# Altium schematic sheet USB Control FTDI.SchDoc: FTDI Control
size 431 x 279 mm; Date: Not shown in title block; ApprovedBy: Not shown in title block; CheckedBy: Not shown in title block; Author: Not shown in title block; CompanyName: Not shown in title block; Engineer: Not shown in title block; Organization: Not shown in title block; Address1: Not shown in title block; Address2: Not shown in title block; Address3: Not shown in title block; Address4: Not shown in title block; DocumentNumber: 1; Revision: Use project parameter SCH_Rev; SheetNumber: 6; SheetTotal: 15; PageSetup: Record=PageOptions¦CenterHorizontal=True¦CenterVertical=True¦PrintScale=1.00¦XCorrection=1.00¦YCorrection=1.00¦PrintKind=0¦BorderSize=5000000¦LeftOffset=0¦BottomOffset=0¦Orientation=2¦PaperLength=1000¦PaperWidth=1000¦Scale=100¦PaperSource=15¦PrintQuality=600¦MediaType=1¦DitherType=10¦PaperKind=Letter¦PrintScaleMode=1
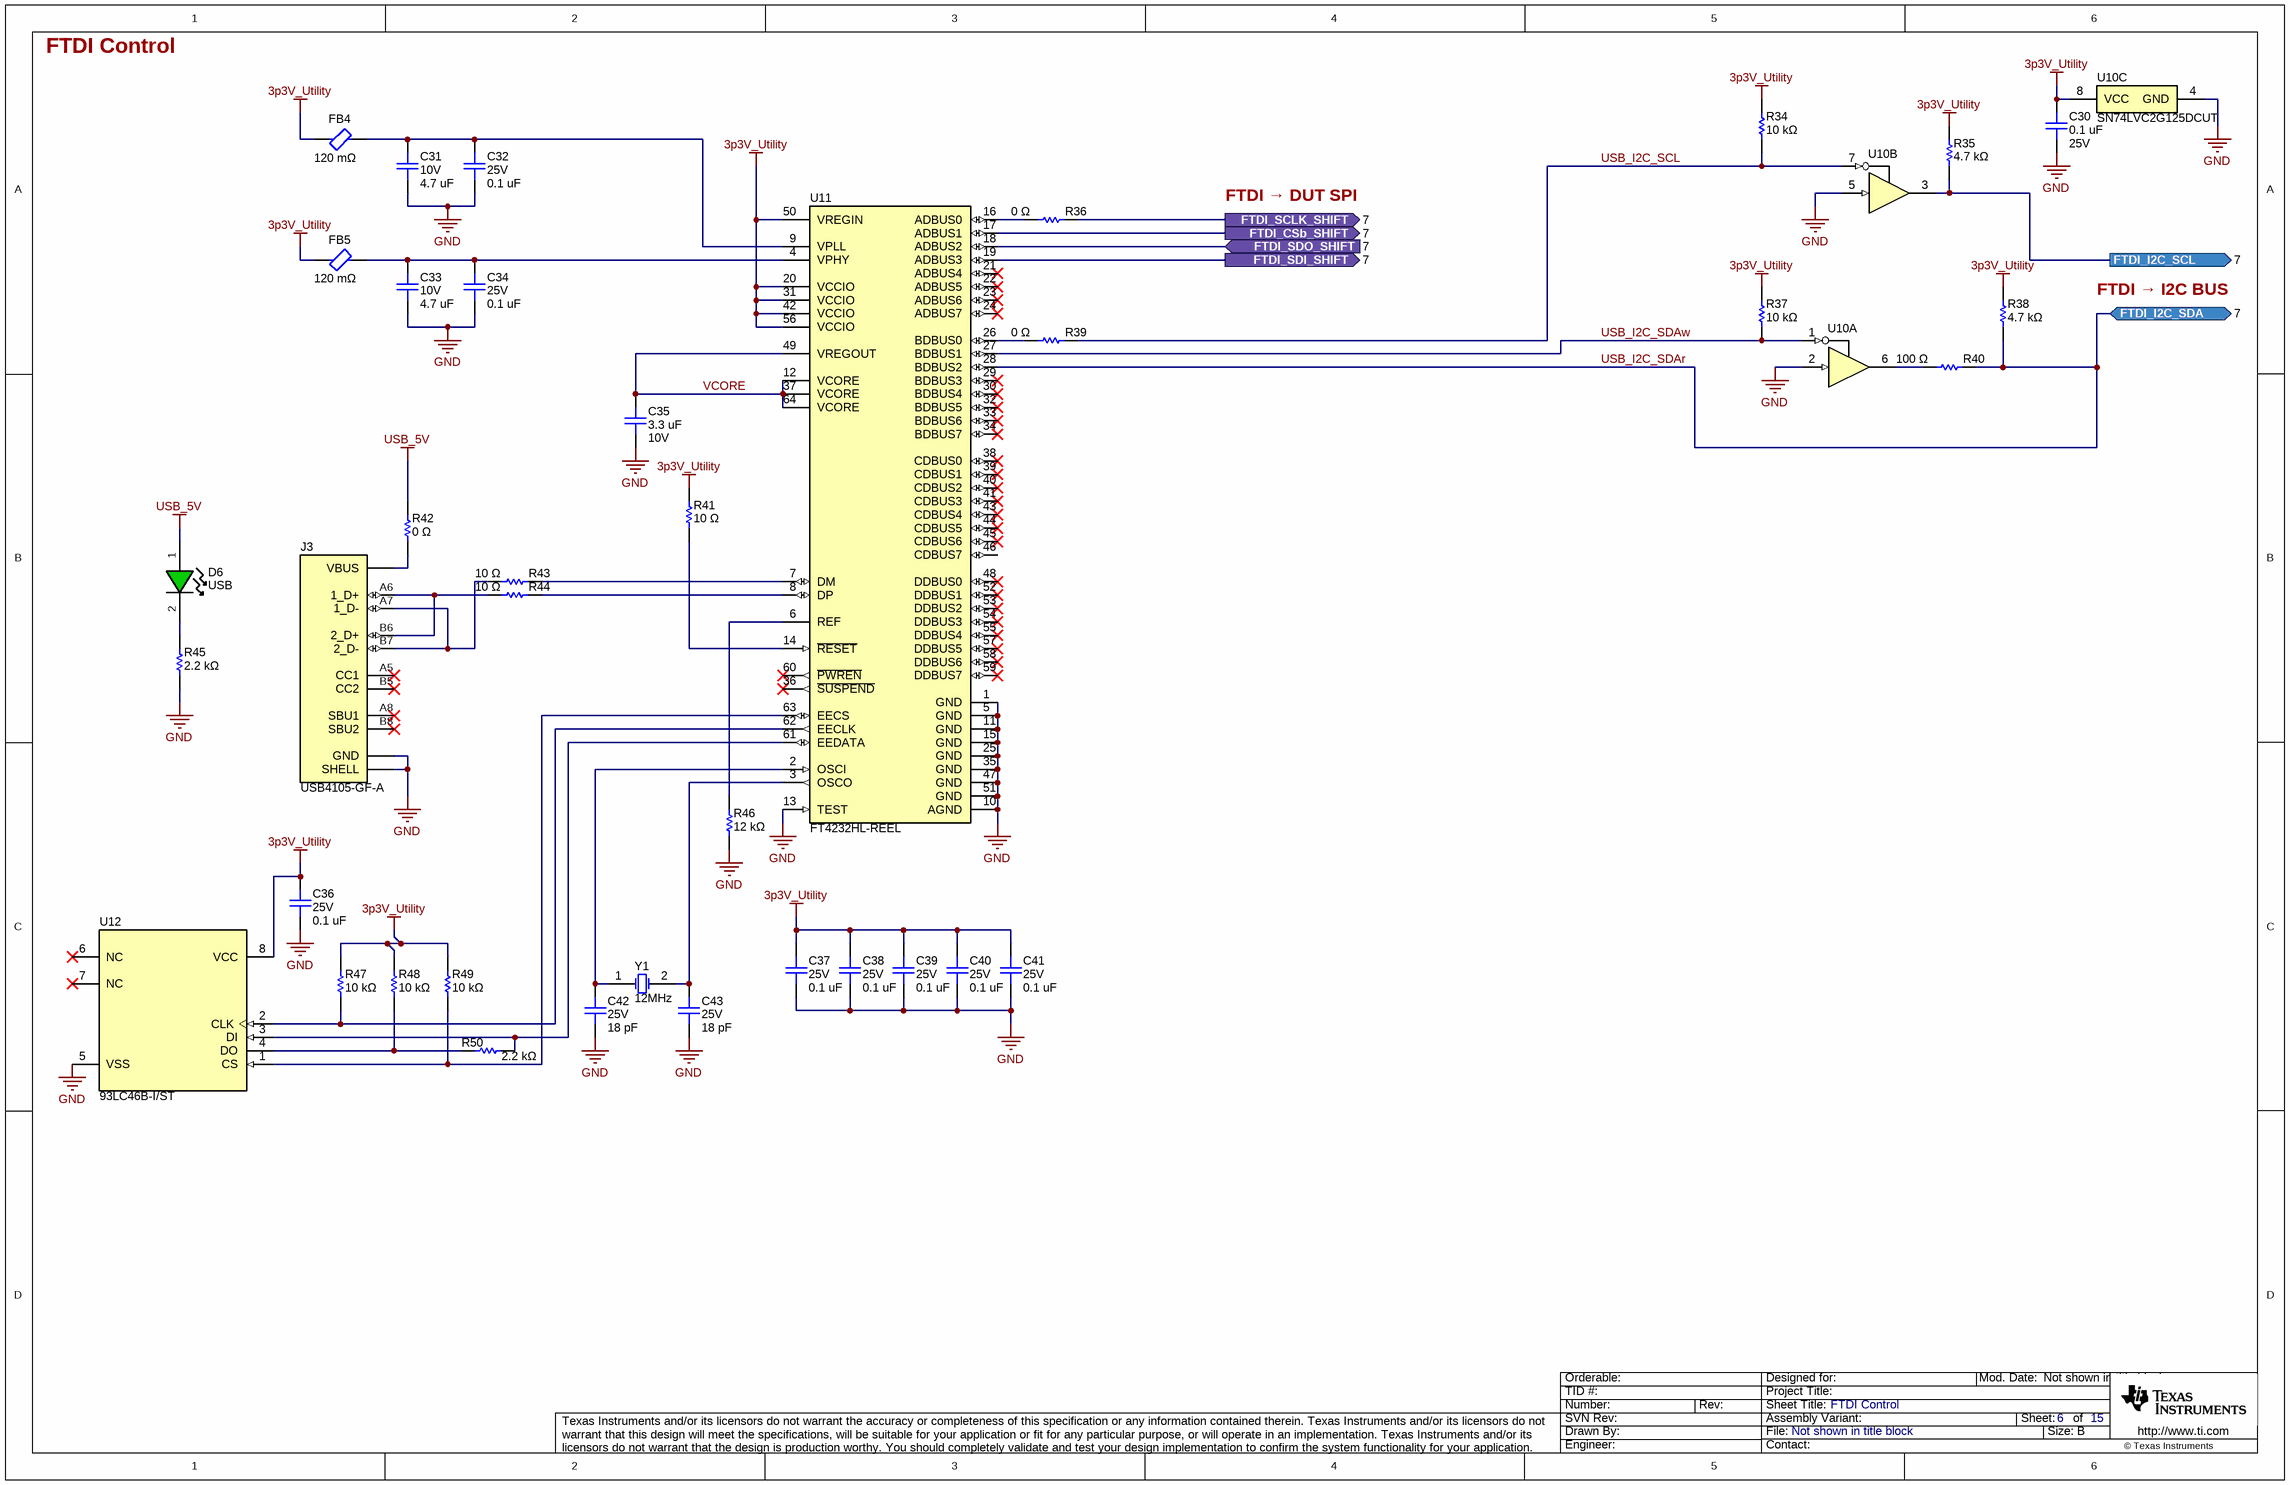
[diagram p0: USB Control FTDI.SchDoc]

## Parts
C30  value 0.1 uF  Voltage - Rated: 25V  [0402L_cap]  (hidden comment: GRT155R71E104KE01J)
C31  value 4.7 uF  Voltage - Rated: 10V  [0402L_cap]  (hidden comment: C1005X5R1A475K050BC)
C32  value 0.1 uF  Voltage - Rated: 25V  [0402L_cap]  (hidden comment: GRT155R71E104KE01J)
C33  value 4.7 uF  Voltage - Rated: 10V  [0402L_cap]  (hidden comment: C1005X5R1A475K050BC)
C34  value 0.1 uF  Voltage - Rated: 25V  [0402L_cap]  (hidden comment: GRT155R71E104KE01J)
C35  value 3.3 uF  Voltage - Rated: 10V  [0603L_cap]  (hidden comment: CGA3E1X5R1A335K080AC)
C36  value 0.1 uF  Voltage - Rated: 25V  [0402L_cap]  (hidden comment: GRT155R71E104KE01J)
C37  value 0.1 uF  Voltage - Rated: 25V  [0402L_cap]  (hidden comment: GRT155R71E104KE01J)
C38  value 0.1 uF  Voltage - Rated: 25V  [0402L_cap]  (hidden comment: GRT155R71E104KE01J)
C39  value 0.1 uF  Voltage - Rated: 25V  [0402L_cap]  (hidden comment: GRT155R71E104KE01J)
C40  value 0.1 uF  Voltage - Rated: 25V  [0402L_cap]  (hidden comment: GRT155R71E104KE01J)
C41  value 0.1 uF  Voltage - Rated: 25V  [0402L_cap]  (hidden comment: GRT155R71E104KE01J)
C42  value 18 pF  Voltage - Rated: 25V  [0201_cap]  (hidden comment: GJM0336C1E180JB01J)
C43  value 18 pF  Voltage - Rated: 25V  [0201_cap]  (hidden comment: GJM0336C1E180JB01J)
D6  Text1: USB  [LED_LTST-C190-Green]  (hidden comment: LTST-C191TGKT)
FB4  DCR: 120 mΩ  [0402L]  (hidden comment: NFZ15SG151SN11D)
FB5  DCR: 120 mΩ  [0402L]  (hidden comment: NFZ15SG151SN11D)
J3  USB4105-GF-A  [FP-USB4105-GF-A_CONN_USB_9MM58_7MM53-MFG]
R34  value 10 kΩ  [0402L]  (hidden comment: ERA-2AEB103X)
R35  value 4.7 kΩ  [0402L]  (hidden comment: ERJ-2RKF4701X)
R36  value 0 Ω  [0201]  (hidden comment: ERJ-1GN0R00C)
R37  value 10 kΩ  [0402L]  (hidden comment: ERA-2AEB103X)
R38  value 4.7 kΩ  [0402L]  (hidden comment: ERJ-2RKF4701X)
R39  value 0 Ω  [0201]  (hidden comment: ERJ-1GN0R00C)
R40  value 100 Ω  [0402L]  (hidden comment: ERJ-2RKF1000X)
R41  value 10 Ω  [0402L]  (hidden comment: ERJ-2GEJ100X)
R42  value 0 Ω  [0805L]  (hidden comment: ERJ-6GEY0R00V)
R43  value 10 Ω  [0402L]  (hidden comment: ERJ-2GEJ100X)
R44  value 10 Ω  [0402L]  (hidden comment: ERJ-2GEJ100X)
R45  value 2.2 kΩ  [0402L]  (hidden comment: ERJ-2GEJ222X)
R46  value 12 kΩ  [0402L]  (hidden comment: ERJ-2RKF1202X)
R47  value 10 kΩ  [0402L]  (hidden comment: ERA-2AEB103X)
R48  value 10 kΩ  [0402L]  (hidden comment: ERA-2AEB103X)
R49  value 10 kΩ  [0402L]  (hidden comment: ERA-2AEB103X)
R50  value 2.2 kΩ  [0402L]  (hidden comment: ERJ-2GEJ222X)
U10  SN74LVC2G125DCUT  [DCU0008A]  (value not drawn)  (parts A,B,C of 3)
U11  FT4232HL-REEL  [LQFP64-MFG]
U12  93LC46B-I/ST  [TSSOP-8]
Y1  Text1: 12MHz  [XTAL_ABM3]  (hidden comment: ABM3-12.000MHZ-D2Y-T)

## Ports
FTDI_CSb_SHIFT (out, see 7), FTDI_I2C_SCL (out, see 7), FTDI_I2C_SDA (bidir, see 7), FTDI_SCLK_SHIFT (out, see 7), FTDI_SDI_SHIFT (out, see 7), FTDI_SDO_SHIFT (in, see 7)

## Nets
3p3V_Utility: C30.2 C36.2 C37.2 C38.2 C39.2 C40.2 C41.2 FB4.1 FB5.1 R34.2 R35.1 R37.2 R38.1 R41.2 R47.2 R48.2 R49.2 U10.8(VCC) U11.20(VCCIO) U11.31(VCCIO) U11.42(VCCIO) U11.50(VREGIN) U11.56(VCCIO) U12.8(VCC)
GND: C30.1 C31.1 C32.1 C33.1 C34.1 C35.1 C36.1 C37.1 C38.1 C39.1 C40.1 C41.1 C42.1 C43.1 J3.1,2,3,4(SHELL) J3.A1,B1(GND) R45.1 R46.1 U10.2(1A) U10.4(GND) U10.5(2A) U11.1(GND) U11.5(GND) U11.10(AGND) U11.11(GND) U11.13(TEST) U11.15(GND) U11.25(GND) U11.35(GND) U11.47(GND) U11.51(GND) U12.5(VSS)
USB_5V: D6.1(A) R42.2
FTDI_CSb_SHIFT: U11.17(ADBUS1) ; port FTDI_CSb_SHIFT
FTDI_I2C_SCL: R35.2 U10.3(2Y) ; port FTDI_I2C_SCL
FTDI_SCLK_SHIFT: R36.2 ; port FTDI_SCLK_SHIFT
FTDI_SDI_SHIFT: U11.19(ADBUS3) ; port FTDI_SDI_SHIFT
FTDI_SDO_SHIFT: U11.18(ADBUS2) ; port FTDI_SDO_SHIFT
USB_I2C_SCL: R34.1 R39.2 U10.7(2~{OE})
USB_I2C_SDAr: R38.2 R40.2 U11.28(BDBUS2) ; port FTDI_I2C_SDA
USB_I2C_SDAw: R37.1 U10.1(1~{OE}) U11.27(BDBUS1)
VCORE: C35.2 U11.12(VCORE) U11.37(VCORE) U11.49(VREGOUT) U11.64(VCORE)
NetC31_2: C31.2 C32.2 FB4.2 U11.9(VPLL)
NetC33_2: C33.2 C34.2 FB5.2 U11.4(VPHY)
NetC42_2: C42.2 U11.2(OSCI) Y1.1(OSC1)
NetC43_2: C43.2 U11.3(OSCO) Y1.2(OSC2)
NetD6_2: D6.2(K) R45.2
NetJ3_A4,B4: J3.A4,B4(VBUS) R42.1
NetJ3_A6: J3.A6(1_D+) J3.B6(2_D+) R44.1
NetJ3_A7: J3.A7(1_D-) J3.B7(2_D-) R43.1
NetR36_1: R36.1 U11.16(ADBUS0)
NetR39_1: R39.1 U11.26(BDBUS0)
NetR40_1: R40.1 U10.6(1Y)
NetR41_1: R41.1 U11.14(~{RESET})
NetR43_2: R43.2 U11.7(DM)
NetR44_2: R44.2 U11.8(DP)
NetR46_2: R46.2 U11.6(REF)
NetR47_1: R47.1 U11.62(EECLK) U12.2(CLK)
NetR48_1: R48.1 R50.1 U12.4(DO)
NetR49_1: R49.1 U11.63(EECS) U12.1(CS)
NetR50_2: R50.2 U11.61(EEDATA) U12.3(DI)

Not connected (* = marked no-connect by the designer): J3 A5(CC1)* A8(SBU1)* B5(CC2)* B8(SBU2)*; U11 21(ADBUS4)* 22(ADBUS5)* 23(ADBUS6)* 24(ADBUS7)* 29(BDBUS3)* 30(BDBUS4)* 32(BDBUS5)* 33(BDBUS6)* 34(BDBUS7)* 36(~{SUSPEND})* 38(CDBUS0)* 39(CDBUS1)* 40(CDBUS2)* 41(CDBUS3)* 43(CDBUS4)* 44(CDBUS5)* 45(CDBUS6)* 46(CDBUS7) 48(DDBUS0)* 52(DDBUS1)* 53(DDBUS2)* 54(DDBUS3)* 55(DDBUS4)* 57(DDBUS5)* 58(DDBUS6)* 59(DDBUS7)* 60(~{PWREN})*; U12 6(NC)* 7(NC)*

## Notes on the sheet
- FTDI → DUT SPI
- FTDI → I2C BUS

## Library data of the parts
C30 C32 C34 C36-C41 = capcc09401: CAP CER 0.1UF 25V X7R 0402; Manufacturer: Murata; CompType: Capacitor Ceramic; Tolerance: ±10%; SizeX_mm: 1; SizeY_mm: 0.5; SizeZ_mm: 0.7
C31 C33 = capcc03298: CAP CER 4.7UF 10V X5R 0402; Manufacturer: TDK Corporation; CompType: Capacitor Ceramic; Tolerance: ±10%; SizeX_mm: 1; SizeY_mm: 0.5; SizeZ_mm: 0.65
C35 = capcc03130: CAP CER 3.3UF 10V X5R 0603; Manufacturer: TDK Corporation; CompType: Capacitor Ceramic; Tolerance: ±10%; SizeX_mm: 1.6; SizeY_mm: 0.8; SizeZ_mm: 0.9
C42 C43 = capcc08580: CAP CER 18PF 25V C0H 0201; Manufacturer: Murata Electronics; CompType: Capacitor Ceramic; Tolerance: ±5%; SizeX_mm: 0.6; SizeY_mm: 0.3; SizeZ_mm: 0.33
D6 = cmp00247: LED GREEN CLEAR CHIP SMD; Manufacturer: Lite-On Inc.; Current Rating (Amps): 20mA; Voltage - Forward (Vf) (Typ): 3.2V; SizeX_mm: 1.6; SizeY_mm: 0.8; SizeZ_mm: 0.65
FB4 FB5 = dcp00209: 0402 (1005) 150OHM (TYP.) 1000MA; Manufacturer: Murata Electronics; Current: 1A
J3 = USB4105-GF-A: USB - C (Type - C) USB 2.0 Receptacle Connector 24 Position Surface Mount, Right Angle; Through Hole; Manufacturer: GCT; CompType: USB C
R34 R37 R47-R49 = RSMD040200315: RES SMD 10K OHM 0.1% 1/16W 0402; Manufacturer: Panasonic Electronic Components; CompType: Resistor SMD; Power (Watts): 0.063W, 1/16W; Temperature Coefficient: ±25ppm/°C; SizeX_mm: 1; SizeY_mm: 0.5; SizeZ_mm: 0.4
R35 R38 = RSMD040202594: RES SMD 4.7K OHM 1% 1/10W 0402; Manufacturer: Panasonic Electronic Components; CompType: Resistor SMD; Power (Watts): 0.1W, 1/10W; Temperature Coefficient: ±100ppm/°C; SizeX_mm: 1; SizeY_mm: 0.5; SizeZ_mm: 0.4
R36 R39 = RSMD020101699: RES SMD 0 OHM JUMPER 1/20W 0201; Manufacturer: Panasonic Electronic Components; CompType: Resistor SMD; Power (Watts): 0.05W, 1/20W
R40 = RSMD040200375: RES SMD 100 OHM 1% 1/10W 0402; Manufacturer: Panasonic Electronic Components; CompType: Resistor SMD; Power (Watts): 0.1W, 1/10W; Temperature Coefficient: ±100ppm/°C; SizeX_mm: 1; SizeY_mm: 0.5; SizeZ_mm: 0.4
R41 R43 R44 = RSMD040200327: RES SMD 10 OHM 5% 1/10W 0402; Manufacturer: Panasonic Electronic Components; CompType: Resistor SMD; Power (Watts): 0.1W, 1/10W; Temperature Coefficient: ±200ppm/°C; SizeX_mm: 1; SizeY_mm: 0.5; SizeZ_mm: 0.4
R42 = RSMD080510615: RES SMD 0 OHM JUMPER 1/8W 0805; Manufacturer: Panasonic Electronic Components; CompType: Resistor SMD; Power (Watts): 0.125W, 1/8W; SizeX_mm: 2; SizeY_mm: 1.25; SizeZ_mm: 0.7
R45 R50 = RSMD040201206: RES SMD 2.2K OHM 5% 1/10W 0402; Manufacturer: Panasonic Electronic Components; CompType: Resistor SMD; Power (Watts): 0.1W, 1/10W; Temperature Coefficient: ±200ppm/°C; SizeX_mm: 1; SizeY_mm: 0.5; SizeZ_mm: 0.4
R46 = RSMD040200519: RES SMD 12K OHM 1% 1/10W 0402; Manufacturer: Panasonic Electronic Components; CompType: Resistor SMD; Power (Watts): 0.1W, 1/10W; Temperature Coefficient: ±100ppm/°C; SizeX_mm: 1; SizeY_mm: 0.5; SizeZ_mm: 0.4
U10 = SN74LVC2G125DCUT: Dual Bus Buffer Gate with 3-State Outputs, DCU0008A (VSSOP-8); Manufacturer: Texas Instruments; F @ Nom Voltage(Max)(Mhz): 150; VCC(Min)(V): 1.65; Bits(#): 2; Output Type: CMOS; Technology Family: LVC; Rating: Catalog; tpd @ Nom Voltage(Max)(ns): 9.1,4.8,4.3,3.7; 3-State Output: Yes; Schmitt Trigger: No; Logic: True; Voltage(Nom)(V): 1.8,2.5,3.3,5; Output Drive (IOL/IOH)(Max)(mA): 32/-32; ICC @ Nom Voltage(Max)(mA): 0.01; Input Type: CMOS/TTL; VCC(Max)(V): 5.5; AEC Category: Q200; AEC Qualified: N; CompType: IC; SizeAreaWB_mm2: 12.6; SizeArea_mm2: 6.4; SizeX_mm: 3.2; SizeY_mm: 2.0; SizeZ_mm: 0.9
U11 = cmp00204: USB Interface IC USB HS to Quad UART/ SPI/JTAG/I2C LQFP-6; Manufacturer: FTDI; Alt PartNumber: FT4232HL-TRAY; Symbol Name: SYM-FT4232HL-REEL; CompType: uC
U12 = cmp00156: 1K Microwire Compatible Serial EEPROM; Manufacturer: Microchip Technology; SymbolCreator: Altium; SizeArea_mm2: 19.2; SizeAreaWB_mm2: 42
Y1 = cmp00323: 12 MHz ±20ppm Crystal 18pF 60 Ohms 2-SMD, No Lead; Manufacturer: Abracon LLC; CompType: XO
